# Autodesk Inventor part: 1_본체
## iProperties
Created: 2015-03
Part Number: 1_본체
Document SubType Name: Modeling
Designer: Administrator
Density: 2.71 g/cm^3
Material: 알루미늄-6061
Mass: 450.719 g
Surface Area: 332.692 cm^2
Volume: 166.317 cm^3
Author: Administrator
